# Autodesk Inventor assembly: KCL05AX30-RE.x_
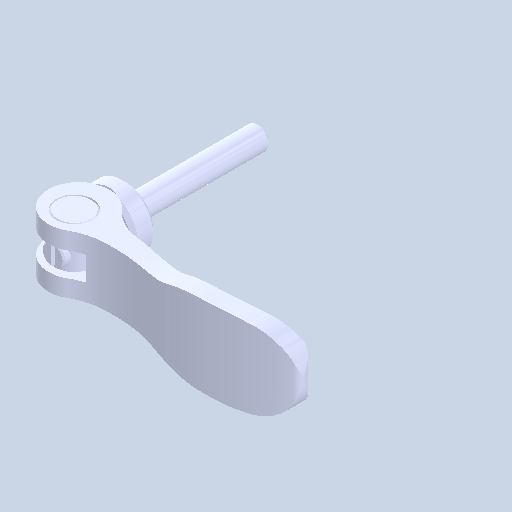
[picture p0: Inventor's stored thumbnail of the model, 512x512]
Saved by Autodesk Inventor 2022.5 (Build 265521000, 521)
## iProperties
Created: 2024-08
Part Number: KCL05AX30-RE.x_
Document SubType Name: Assembly
Designer: ImaoCorp
Author: ImaoCorp
Sending System: SOLIDWORKS 2022-2022290
MC: AMD64
MC_MODEL: Intel64 Family 6 Model 60 Stepping 3, GenuineIntel
OS: Windows_NT
FRU: Parasolid Version 33.1, build 260,  4-25-2022
FORMAT: text
GUISE: transmit
KEY: FILEKCL05AX30-RE.x_t
DATE: Thu Aug 29 10:48:35 2024
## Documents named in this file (5)
- Y:\5.更新分\2024年対応\1001_KCL\データ\kcl05ax30-re\KCL05AX30-RE.x_.iam
- Y:\5.更新分\2024年対応\1001_KCL\データ\kcl05ax30-re\KCL05AX30-RE_01.ipt
- Y:\5.更新分\2024年対応\1001_KCL\データ\kcl05ax30-re\KCL05AX30-RE_02.ipt
- Y:\5.更新分\2024年対応\1001_KCL\データ\kcl05ax30-re\KCL05AX30-RE_03.ipt
- Y:\5.更新分\2024年対応\1001_KCL\データ\kcl05ax30-re\KCL05AX30-RE_04.ipt
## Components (4 placed, 4 different names)
1. KCL05AX30-RE_01
2. KCL05AX30-RE_02
3. KCL05AX30-RE_03
4. KCL05AX30-RE_04
